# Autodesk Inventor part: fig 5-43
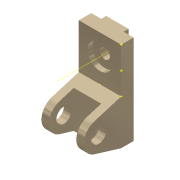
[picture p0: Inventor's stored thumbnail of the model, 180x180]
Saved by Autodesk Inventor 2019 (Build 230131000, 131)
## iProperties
Shininess: 65.0
Angle Display Precision: 2
Document Length Units: 11269
Document Angle Units: 11279
Document Time Units: 11290
Document Mass Units: 11283
Document Length Units Precision: 3
Document Angle Units Precision: 2
Created: 2001-11
Part Number: fig 5-43
Document SubType Name: Modeling
Designer: Renu Muthoo
Density: 1 g/cm^3
Material: Generic
Appearance: Metal-Titanium (Polished)
Density: 0.0
Volumn: 0.0
Area: 0.0
PropertySet Name: Model Information
Control State: 0
Master: False
Checked Out: False
Author: Renu Muthoo
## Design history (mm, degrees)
node "Sketch1"
sketch "Sketch2"
  geometry: L1 (33.257, 104.664)-(33.257, -75.336); L2 (33.257, -75.336)-(8.257, -75.336); L3 (8.257, -75.336)-(-45.451, -59.045); L4 (-45.451, -1.628)-(8.257, 14.664); L5 (8.257, 14.664)-(8.257, 104.664); L6 (8.257, 104.664)-(33.257, 104.664); C1 r 15 at (-36.743, -30.336); A1 r 30 centre (-36.743, -30.336) between (-45.451, -1.628) and (-45.451, -59.045)
  constraints: 12 end point, 2 centre point, 2 equal length, 2 parallel, 2 point on circle, 2 tangent, 1 coincident, 1 perpendicular, 1 vertical
  dimensions: "d0" = 180 distance of L1.start L1.end; "d1" = 30 radius of A1; "d2" = 25 distance of L5.end L1.start; "d3" = 45 distance from line of L2 A1.centre; "d4" = 70 distance from line of L1 A1.centre; "d5" = 30 diameter of C1
extrude "Extrusion1" new body sketch "Sketch2" distance "d6" = 85; taper "d7" = 0 deg
workplane "Work Plane1"
sketch "Sketch3"
  geometry: L1 (15, 62.364)-(70, 62.364); L2 (70, 62.364)-(70, -52.386); L3 (70, -52.386)-(15, -52.386); L4 (15, -52.386)-(15, 62.364); L5 (0, -45)-(0, -28.708) reference
  constraints: 8 end point, 2 parallel, 1 horizontal, 1 perpendicular
  dimensions: "d8" = 55 distance of L1.start L1.end; "d9" = 15 distance between parallel lines of L5 L4
extrude "Extrusion2" cut sketch "Sketch3" distance "d10" = 50; taper "d11" = 0 deg
sketch "Sketch4"
  geometry: L1 (0, 25)-(85, 25) reference; L2 (0, 0)-(0, 25) reference; L3 (20, 25)-(65, 25); L4 (65, 25)-(65, 35); L5 (65, 35)-(20, 35); L6 (20, 35)-(20, 25)
  constraints: 8 end point, 2 parallel, 1 horizontal, 1 perpendicular, 1 point on line
  dimensions: "d12" = 45 distance of L4.end L5.end; "d13" = 10 distance of L3.end L4.end; "d14" = 20 distance between parallel lines of L2 L6
extrude "Extrusion3" join sketch "Sketch4" stored distance "d15" = 50; taper "d16" = 0 deg
sketch "Sketch5"
  geometry: L1 (85, 0)-(85, 90) reference; L2 (0, 90)-(85, 90) reference; 1 further point
  dimensions: "d17" = 42 distance from line of L2 point (42.5, 48); "d18" = 42.5 distance from line of L1 point (42.5, 48)
hole "Hole1" sketch "Sketch5" at (42.5, 48) diameter "d19" = 20; stored, may be unused: countersink angle "d23" = 82 deg, drill point angle "d25" = 118 deg; dims "d20" = 6, "d21" = 50, "d22" = 10, "d24" = 8
workpoint "Work Point1"
workpoint "Work Point2"
workpoint "Work Point3"
workpoint "Work Point4"
workaxis "Work Axis2"
body "Solid1"
